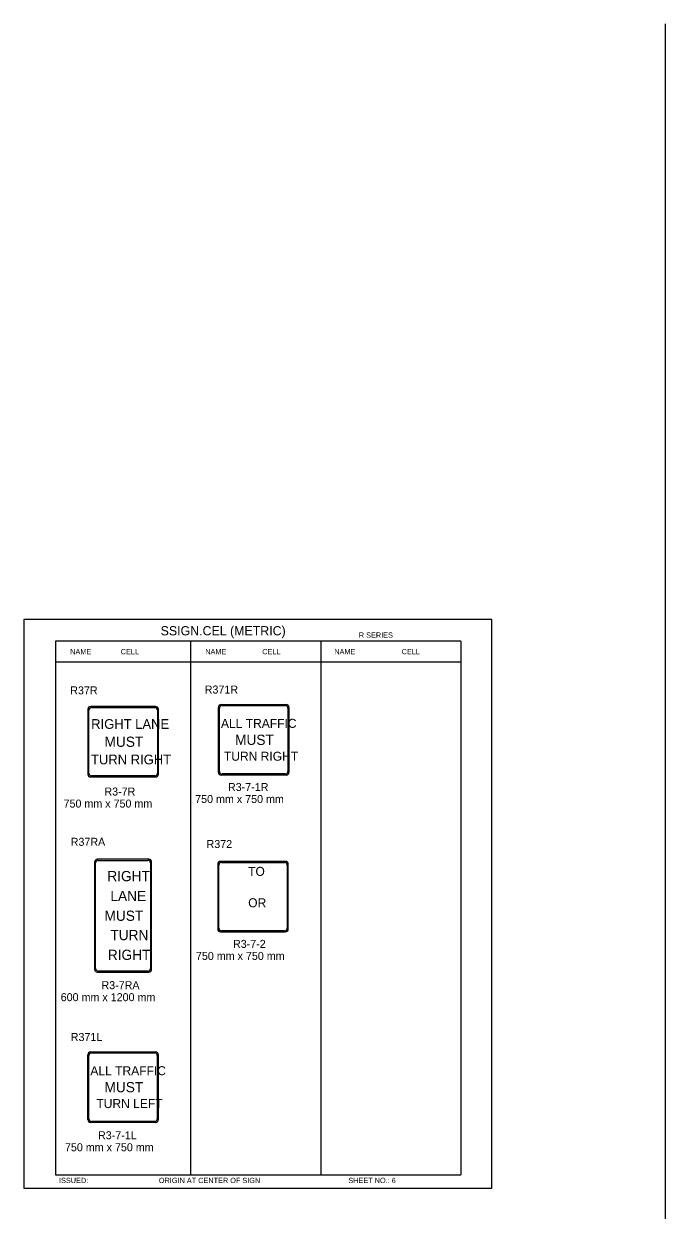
# Model space of a CAD drawing. Extents: x -12 to 6962, y -3756 to 679.
# Drawn here: x 1018.1 to 1258.3, y 217 to 661.7 of the extents above; entities that cross this region are included whole.
import ezdxf

# ---------------------------------------------------------------- set-up
doc = ezdxf.new("R2010")
doc.units = 0
for name, color, linetype in [('Level 1', 7, 'Continuous'), ('Level 2', 7, 'Continuous'), ('Level 3', 7, 'Continuous'), ('Level 63', 7, 'Continuous')]:
    doc.layers.add(name, color=color, linetype=linetype)

msp = doc.modelspace()

# ---------------------------------------------------------------- linework, layer by layer
at = {"layer": 'Level 1'}
for p, q in [((1181.72, 430.35), (1029.96, 430.35)), ((1029.96, 430.35), (1029.96, 230.35)), ((1080.55, 430.35), (1080.55, 230.35)), ((1129.33, 430.35), (1129.33, 230.35)), ((1181.72, 430.35), (1181.72, 230.35)), ((1181.72, 422.43), (1029.96, 422.43)), ((1043.47, 405.43), (1067.14, 405.43)), ((1090.99, 381.18), (1090.99, 405.48)), ((1091.38, 381.49), (1091.38, 405.17)), ((1092.05, 406.54), (1116.35, 406.54)), ((1092.36, 406.15), (1116.03, 406.15)), ((1117.01, 405.17), (1117.01, 381.49)), ((1117.4, 405.48), (1117.4, 381.18)), ((1042.49, 380.77), (1042.49, 404.45)), ((1068.12, 404.45), (1068.12, 380.77)), ((1055.3, 392.61), (1055.3, 392.61)), ((1104.2, 393.33), (1104.2, 393.33)), ((1067.14, 379.8), (1043.47, 379.8)), ((1116.35, 380.12), (1092.05, 380.12)), ((1116.03, 380.52), (1092.36, 380.52)), ((1045.01, 307.65), (1045.01, 347.18)), ((1045.99, 348.16), (1064.58, 348.16)), ((1065.56, 347.18), (1065.56, 307.65)), ((1092.12, 347.39), (1115.8, 347.39)), ((1091.14, 322.73), (1091.14, 346.41)), ((1116.77, 346.41), (1116.77, 322.73)), ((1103.96, 334.57), (1103.96, 334.57)), ((1055.29, 327.42), (1055.29, 327.42)), ((1115.8, 321.76), (1092.12, 321.76)), ((1064.58, 306.68), (1045.99, 306.68)), ((1043.45, 275.99), (1067.12, 275.99)), ((1042.47, 251.34), (1042.47, 275.01)), ((1068.1, 275.01), (1068.1, 251.34)), ((1055.29, 263.18), (1055.29, 263.18)), ((1067.12, 250.36), (1043.45, 250.36)), ((1029.96, 230.35), (1181.72, 230.35))]:
    msp.add_line(p, q, dxfattribs=at)
for centre, radius, start, end in [((1043.47, 404.45), 0.977, 90, 180), ((1067.14, 404.45), 0.977, 0, 90), ((1092.05, 405.48), 1.06, 90, 180), ((1092.36, 405.17), 0.977, 90, 180), ((1116.03, 405.17), 0.977, 0, 90), ((1116.35, 405.48), 1.06, 0, 90), ((1043.47, 380.77), 0.977, 180, 270), ((1067.14, 380.77), 0.977, 270, 0), ((1092.05, 381.18), 1.06, 180, 270), ((1092.36, 381.49), 0.977, 180, 270), ((1116.03, 381.49), 0.977, 270, 0), ((1116.35, 381.18), 1.06, 270, 0), ((1045.99, 347.18), 0.977, 90, 180), ((1064.58, 347.18), 0.977, 0, 90), ((1092.12, 346.41), 0.977, 90, 180), ((1115.8, 346.41), 0.977, 0, 90), ((1092.12, 322.73), 0.977, 180, 270), ((1115.8, 322.73), 0.977, 270, 0), ((1045.99, 307.65), 0.977, 180, 270), ((1064.58, 307.65), 0.977, 270, 0), ((1043.45, 275.01), 0.977, 90, 180), ((1067.12, 275.01), 0.977, 0, 90), ((1043.45, 251.34), 0.977, 180, 270), ((1067.12, 251.34), 0.977, 270, 0)]:
    msp.add_arc(centre, radius, start, end, dxfattribs=at)
at = {"layer": 'Level 3'}
for p, q in [((1258.34, 661.66), (1258.34, -1225.34)), ((1042.1, 404.76), (1042.1, 380.46)), ((1067.45, 405.82), (1043.15, 405.82)), ((1068.51, 380.46), (1068.51, 404.76)), ((1090.99, 381.18), (1090.99, 405.48)), ((1092.05, 406.54), (1116.35, 406.54)), ((1117.4, 405.48), (1117.4, 381.18)), ((1043.15, 379.41), (1067.45, 379.41)), ((1116.35, 380.12), (1092.05, 380.12)), ((1044.62, 347.49), (1044.62, 307.34)), ((1064.9, 348.55), (1045.67, 348.55)), ((1065.95, 307.34), (1065.95, 347.49)), ((1116.11, 347.78), (1091.81, 347.78)), ((1090.75, 346.72), (1090.75, 322.42)), ((1117.17, 322.42), (1117.17, 346.72)), ((1091.81, 321.36), (1116.11, 321.36)), ((1045.67, 306.28), (1064.9, 306.28)), ((1043.13, 276.38), (1067.44, 276.38)), ((1042.08, 251.02), (1042.08, 275.33)), ((1068.49, 275.33), (1068.49, 251.02)), ((1067.44, 249.97), (1043.13, 249.97))]:
    msp.add_line(p, q, dxfattribs=at)
for centre, start, end in [((1043.15, 404.76), 90, 180), ((1067.45, 404.76), 0, 90), ((1092.05, 405.48), 90, 180), ((1116.35, 405.48), 0, 90), ((1043.15, 380.46), 180, 270), ((1067.45, 380.46), 270, 0), ((1092.05, 381.18), 180, 270), ((1116.35, 381.18), 270, 0), ((1045.67, 347.49), 90, 180), ((1064.9, 347.49), 0, 90), ((1091.81, 346.72), 90, 180), ((1116.11, 346.72), 0, 90), ((1091.81, 322.42), 180, 270), ((1116.11, 322.42), 270, 0), ((1045.67, 307.34), 180, 270), ((1064.9, 307.34), 270, 0), ((1043.13, 275.33), 90, 180), ((1067.44, 275.33), 0, 90), ((1043.13, 251.02), 180, 270), ((1067.44, 251.02), 270, 0)]:
    msp.add_arc(centre, 1.06, start, end, dxfattribs=at)
at = {"layer": 'Level 63'}
msp.add_lwpolyline([(1018.09, 225.31), (1193.35, 225.31), (1193.35, 438.4), (1018.09, 438.4)], close=True, dxfattribs=at)

# ---------------------------------------------------------------- texts
at = {"layer": 'Level 1'}
for s, height, p in [('RIGHT LANE', 3.639, (1043.34, 397.44)), ('ALL TRAFFIC', 3.3704, (1091.95, 397.81)), ('MUST', 3.83, (1048.35, 390.7)), ('MUST', 3.83, (1097.24, 391.42)), ('TURN RIGHT', 3.639, (1043.28, 384.14)), ('TURN RIGHT', 3.37, (1093.06, 385.49)), ('RIGHT', 3.83, (1049.4, 340.35)), ('TO', 3.37, (1102.11, 342.35)), ('LANE', 3.83, (1050.55, 332.89)), ('OR', 3.37, (1102.15, 330.59)), ('MUST', 3.83, (1048.33, 325.5)), ('TURN', 3.83, (1050.54, 318.25)), ('RIGHT', 3.83, (1049.57, 310.85)), ('ALL TRAFFIC', 3.3704, (1043.04, 267.65)), ('MUST', 3.83, (1048.33, 261.26)), ('TURN LEFT', 3.37, (1045.3, 255.33))]:
    msp.add_text(s, height=height, dxfattribs=at).set_placement(p)
at = {"layer": 'Level 2'}
for s, p in [('R371R', (1085.87, 410.66)), ('R37R', (1035.5, 410.36)), ('R37RA', (1035.67, 353.61)), ('R372', (1086.55, 352.78)), ('R371L', (1035.69, 280.47))]:
    msp.add_text(s, height=3, dxfattribs=at).set_placement(p)
at = {"layer": 'Level 3'}
for s, height, p in [('SSIGN.CEL (METRIC)', 3.4642, (1069.35, 432.46)), ('R SERIES', 1.979, (1143.59, 431.59)), ('NAME', 1.98, (1035.48, 425.39)), ('CELL', 1.98, (1054.4, 425.39)), ('NAME', 1.98, (1086.06, 425.39)), ('CELL', 1.98, (1107.42, 425.39)), ('NAME', 1.98, (1134.39, 425.39)), ('CELL', 1.98, (1159.62, 425.39)), ('R3-7R', 3, (1048.29, 372.44)), ('R3-7-1R', 3, (1094.57, 374.14)), ('750 mm x 750 mm', 3, (1033, 367.94)), ('750 mm x 750 mm', 3, (1082.28, 369.64)), ('R3-7-2', 3, (1096.45, 315.35)), ('750 mm x 750 mm', 3, (1082.57, 310.85)), ('R3-7RA', 3, (1047.18, 299.89)), ('600 mm x 1200 mm', 3, (1031.93, 295.39)), ('R3-7-1L', 3, (1045.9, 243.65)), ('750 mm x 750 mm', 3, (1033.52, 239.15)), ('ISSUED:', 1.98, (1031.3, 227.23)), ('ORIGIN AT CENTER OF SIGN', 1.9795, (1068.69, 227.23)), ('SHEET NO.: 6', 1.9795, (1139.65, 227.23))]:
    msp.add_text(s, height=height, dxfattribs=at).set_placement(p)

doc.saveas('drawing.dxf')
